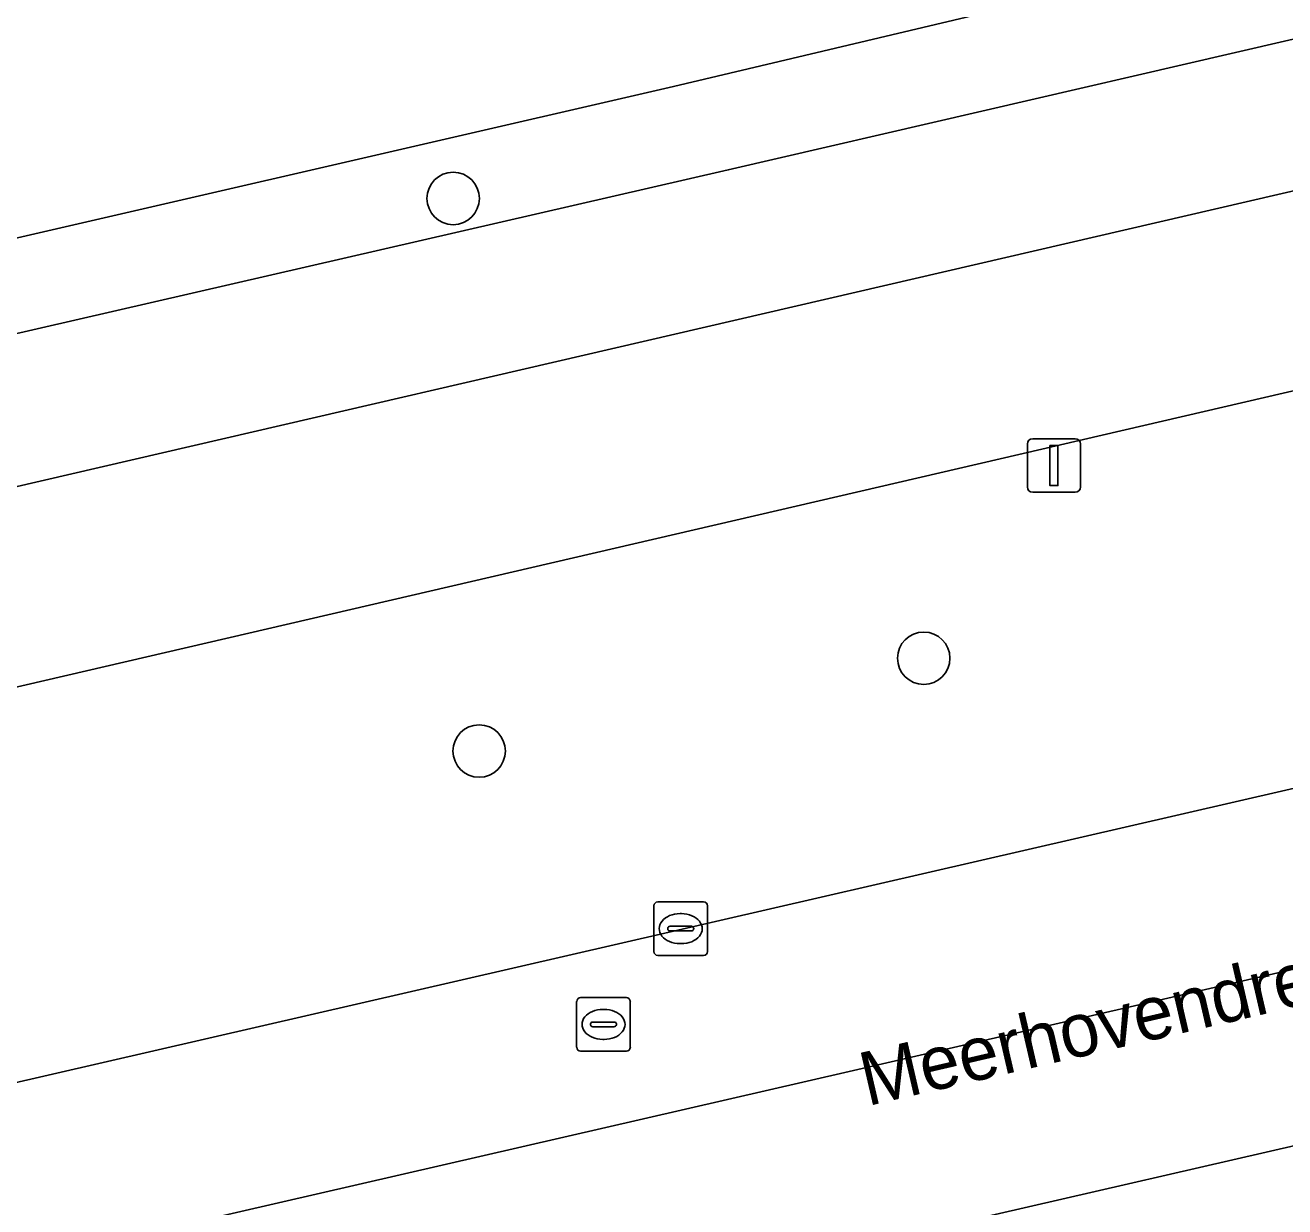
# Model space of a CAD drawing. Extents: x 156412 to 157779, y 382335 to 383768.
# Drawn here: x 157056.03 to 157079.52, y 383007.95 to 383030 of the extents above; entities that cross this region are included whole.
import ezdxf

# ---------------------------------------------------------------- set-up
doc = ezdxf.new("R2010")
doc.units = 0
for name, color, linetype in [('IMGEO_Berm_groen', 7, 'Continuous'), ('IMGEO_Boom', 7, 'Continuous'), ('IMGEO_Fietspad_gesloten', 7, 'Continuous'), ('IMGEO_Kolk', 7, 'Continuous'), ('IMGEO_Lichtmast', 7, 'Continuous'), ('IMGEO_Openbare_ruimte_label', 7, 'Continuous'), ('IMGEO_Parkeervlak_open', 7, 'Continuous'), ('IMGEO_Rijbaan_lokaal_gesloten', 7, 'Continuous'), ('IMGEO_Rijbaan_regionaal_gesloten', 7, 'Continuous'), ('IMGEO_Rioolput', 7, 'Continuous')]:
    doc.layers.add(name, color=color, linetype=linetype)

msp = doc.modelspace()

# ---------------------------------------------------------------- linework, layer by layer
at = {"layer": 'IMGEO_Berm_groen'}
for points in [[(157134.668, 383046.231), (157133.887, 383045.692), (157132.892, 383044.965), (157131.807, 383044.306), (157130.652, 383043.778), (157130.127, 383043.549), (157130.075, 383043.523), (157130.648, 383041.534), (157069.138, 383027.297), (157007.744, 383013.169), (157007.809, 383012.863), (157007.932, 383012.29), (157010.107, 383012.383)], [(157025.431, 383014.337), (157134.445, 383039.6)], [(157120.078, 383025.139), (157123.21, 383025.803), (157135.435, 383028.656), (157133.846, 383035.729), (157125.414, 383033.797), (157049.55, 383016.188), (157025.969, 383010.873)], [(157019.53, 383009.614), (157021.079, 383002.266), (157086.233, 383017.27), (157120.078, 383025.139)], [(157126.773, 383019.975), (157107.253, 383015.436), (157011.566, 382993.422)]]:
    msp.add_lwpolyline(points, dxfattribs=at)
at = {"layer": 'IMGEO_Boom'}
for centre in [(157064.008, 383026.764), (157072.785, 383018.187), (157064.493, 383016.456)]:
    msp.add_circle(centre, 0.489, dxfattribs=at)
at = {"layer": 'IMGEO_Fietspad_gesloten'}
for points in [[(157025.969, 383010.873), (157049.55, 383016.188), (157125.414, 383033.797), (157133.846, 383035.729), (157137.616, 383036.593), (157138.658, 383036.824), (157141.7, 383037.545), (157144.238, 383038.146), (157146.809, 383038.714), (157252.088, 383062.977)], [(157134.445, 383039.6), (157025.431, 383014.337)]]:
    msp.add_lwpolyline(points, dxfattribs=at)
at = {"layer": 'IMGEO_Kolk'}
for p, q in [((157067.751, 383012.717), (157067.751, 383013.569)), ((157067.826, 383013.643), (157068.678, 383013.643)), ((157068.752, 383013.569), (157068.752, 383012.717)), ((157068.239, 383013.423), (157068.264, 383013.423)), ((157068.01, 383013.137), (157068.01, 383013.149)), ((157068.448, 383013.1), (157068.05, 383013.1)), ((157068.053, 383013.186), (157068.451, 383013.186)), ((157068.494, 383013.149), (157068.494, 383013.137)), ((157068.262, 383012.863), (157068.237, 383012.863)), ((157068.678, 383012.643), (157067.826, 383012.643))]:
    msp.add_line(p, q, dxfattribs=at)
for points in [[(157067.751, 383012.717), (157067.751, 383013.569)], [(157067.826, 383013.643), (157068.678, 383013.643)], [(157068.752, 383013.569), (157068.752, 383012.717)], [(157068.678, 383012.643), (157067.826, 383012.643)]]:
    msp.add_lwpolyline(points, dxfattribs=at)
for centre, radius, start, end in [((157067.828, 383013.567), 0.0765, 91.552, 178.448), ((157067.828, 383013.567), 0.0765, 91.552, 178.448), ((157068.676, 383013.567), 0.0765, 1.552, 88.448), ((157068.676, 383013.567), 0.0765, 1.552, 88.448), ((157068.05, 383013.146), 0.0403, 85.8775, 175.7526), ((157068.047, 383013.136), 0.0366, 178.938, 274.7102), ((157068.451, 383013.143), 0.043, 264.8664, 352.4533), ((157068.455, 383013.148), 0.0386, 1.7309, 96.639), ((157067.828, 383012.719), 0.0765, 181.552, 268.448), ((157067.828, 383012.719), 0.0765, 181.552, 268.448), ((157068.676, 383012.719), 0.0765, 271.552, 358.448), ((157068.676, 383012.719), 0.0765, 271.552, 358.448)]:
    msp.add_arc(centre, radius, start, end, dxfattribs=at)
for centre, major_axis, ratio, start_param, end_param in [((157068.238, 383013.143), (-0.387, 0.002), 0.722429, 4.712389, 7.853982), ((157068.263, 383013.143), (-0.39, 0.002), 0.717154, 1.570796, 4.712389)]:
    msp.add_ellipse(centre, major_axis=major_axis, ratio=ratio, start_param=start_param, end_param=end_param, dxfattribs=at)
at = {"layer": 'IMGEO_Lichtmast'}
for p, q in [((157074.718, 383021.383), (157074.718, 383022.183)), ((157074.718, 383022.183), (157074.718, 383021.383)), ((157074.818, 383022.283), (157075.608, 383022.283)), ((157075.608, 383022.283), (157074.818, 383022.283)), ((157075.708, 383022.183), (157075.708, 383021.383)), ((157075.708, 383021.383), (157075.708, 383022.183)), ((157075.608, 383021.283), (157074.818, 383021.283)), ((157074.818, 383021.283), (157075.608, 383021.283))]:
    msp.add_line(p, q, dxfattribs=at)
msp.add_lwpolyline([(157075.138, 383022.158), (157075.288, 383022.158), (157075.288, 383021.408), (157075.138, 383021.408), (157075.138, 383022.158)], dxfattribs=at)
for centre, start, end in [((157074.818, 383022.183), 90, 180), ((157074.818, 383022.183), 90, 180), ((157075.608, 383022.183), 0, 90), ((157075.608, 383022.183), 360, 90), ((157074.818, 383021.383), 180, 270), ((157074.818, 383021.383), 180, 270), ((157075.608, 383021.383), 270, 0), ((157075.608, 383021.383), 270, 0)]:
    msp.add_arc(centre, 0.1, start, end, dxfattribs=at)
at = {"layer": 'IMGEO_Parkeervlak_open'}
msp.add_lwpolyline([(157130.648, 383041.534), (157130.075, 383043.523), (157068.115, 383028.853), (157007.386, 383014.842), (157007.744, 383013.169), (157069.138, 383027.297)], close=True, dxfattribs=at)
at = {"layer": 'IMGEO_Rijbaan_lokaal_gesloten'}
msp.add_lwpolyline([(157007.077, 383015.137), (157007.312, 383015.191), (157007.386, 383014.842), (157068.115, 383028.853), (157130.075, 383043.523)], dxfattribs=at)
at = {"layer": 'IMGEO_Rijbaan_regionaal_gesloten'}
for points in [[(157141.179, 383026.512), (157140.296, 383029.792), (157138.951, 383029.477), (157135.435, 383028.656), (157123.21, 383025.803), (157120.078, 383025.139), (157086.233, 383017.27), (157021.079, 383002.266), (157010.025, 382999.721), (157006.286, 382998.858), (157006.14, 382998.823), (157001.796, 382997.802), (156998.557, 382997.047)], [(156997.919, 382997.431), (156998.833, 382993.499), (157040.159, 383003.288), (157114.05, 383020.299), (157141.179, 383026.512)], [(157138.154, 383023.651), (157141.527, 383025.221), (157141.179, 383026.512), (157114.05, 383020.299), (157040.159, 383003.288), (156998.833, 382993.499), (156999.747, 382989.567)], [(157000.433, 382990.789), (157003.301, 382991.466), (157007.607, 382992.461), (157011.566, 382993.422), (157107.253, 383015.436)]]:
    msp.add_lwpolyline(points, dxfattribs=at)
at = {"layer": 'IMGEO_Rioolput'}
for p, q in [((157066.386, 383011.857), (157067.238, 383011.857)), ((157066.311, 383010.931), (157066.311, 383011.783)), ((157066.799, 383011.637), (157066.824, 383011.637)), ((157067.312, 383011.783), (157067.312, 383010.931)), ((157066.57, 383011.351), (157066.57, 383011.363)), ((157066.613, 383011.4), (157067.011, 383011.4)), ((157067.054, 383011.363), (157067.054, 383011.351)), ((157067.008, 383011.314), (157066.61, 383011.314)), ((157066.822, 383011.077), (157066.797, 383011.077)), ((157067.238, 383010.857), (157066.386, 383010.857))]:
    msp.add_line(p, q, dxfattribs=at)
for points in [[(157066.386, 383011.857), (157067.238, 383011.857)], [(157066.311, 383010.931), (157066.311, 383011.783)], [(157067.312, 383011.783), (157067.312, 383010.931)], [(157067.238, 383010.857), (157066.386, 383010.857)]]:
    msp.add_lwpolyline(points, dxfattribs=at)
for centre, radius, start, end in [((157066.388, 383011.781), 0.0765, 91.552, 178.448), ((157066.388, 383011.781), 0.0765, 91.552, 178.448), ((157067.236, 383011.781), 0.0765, 1.552, 88.448), ((157067.236, 383011.781), 0.0765, 1.552, 88.448), ((157066.61, 383011.36), 0.0403, 85.8775, 175.7526), ((157066.607, 383011.35), 0.0366, 178.938, 274.7102), ((157067.011, 383011.357), 0.043, 264.8664, 352.4533), ((157067.015, 383011.362), 0.0386, 1.7309, 96.639), ((157066.388, 383010.933), 0.0765, 181.552, 268.448), ((157066.388, 383010.933), 0.0765, 181.552, 268.448), ((157067.236, 383010.933), 0.0765, 271.552, 358.448), ((157067.236, 383010.933), 0.0765, 271.552, 358.448)]:
    msp.add_arc(centre, radius, start, end, dxfattribs=at)
for centre, major_axis, ratio, start_param, end_param in [((157066.798, 383011.357), (-0.387, 0.002), 0.722429, 4.712389, 7.853982), ((157066.823, 383011.357), (-0.39, 0.002), 0.717154, 1.570796, 4.712389)]:
    msp.add_ellipse(centre, major_axis=major_axis, ratio=ratio, start_param=start_param, end_param=end_param, dxfattribs=at)

# ---------------------------------------------------------------- texts
at = {"layer": 'IMGEO_Openbare_ruimte_label'}
msp.add_text('Meerhovendreef', height=1, rotation=13.0633, dxfattribs=at).set_placement((157071.731, 383009.829))

doc.saveas('drawing.dxf')
